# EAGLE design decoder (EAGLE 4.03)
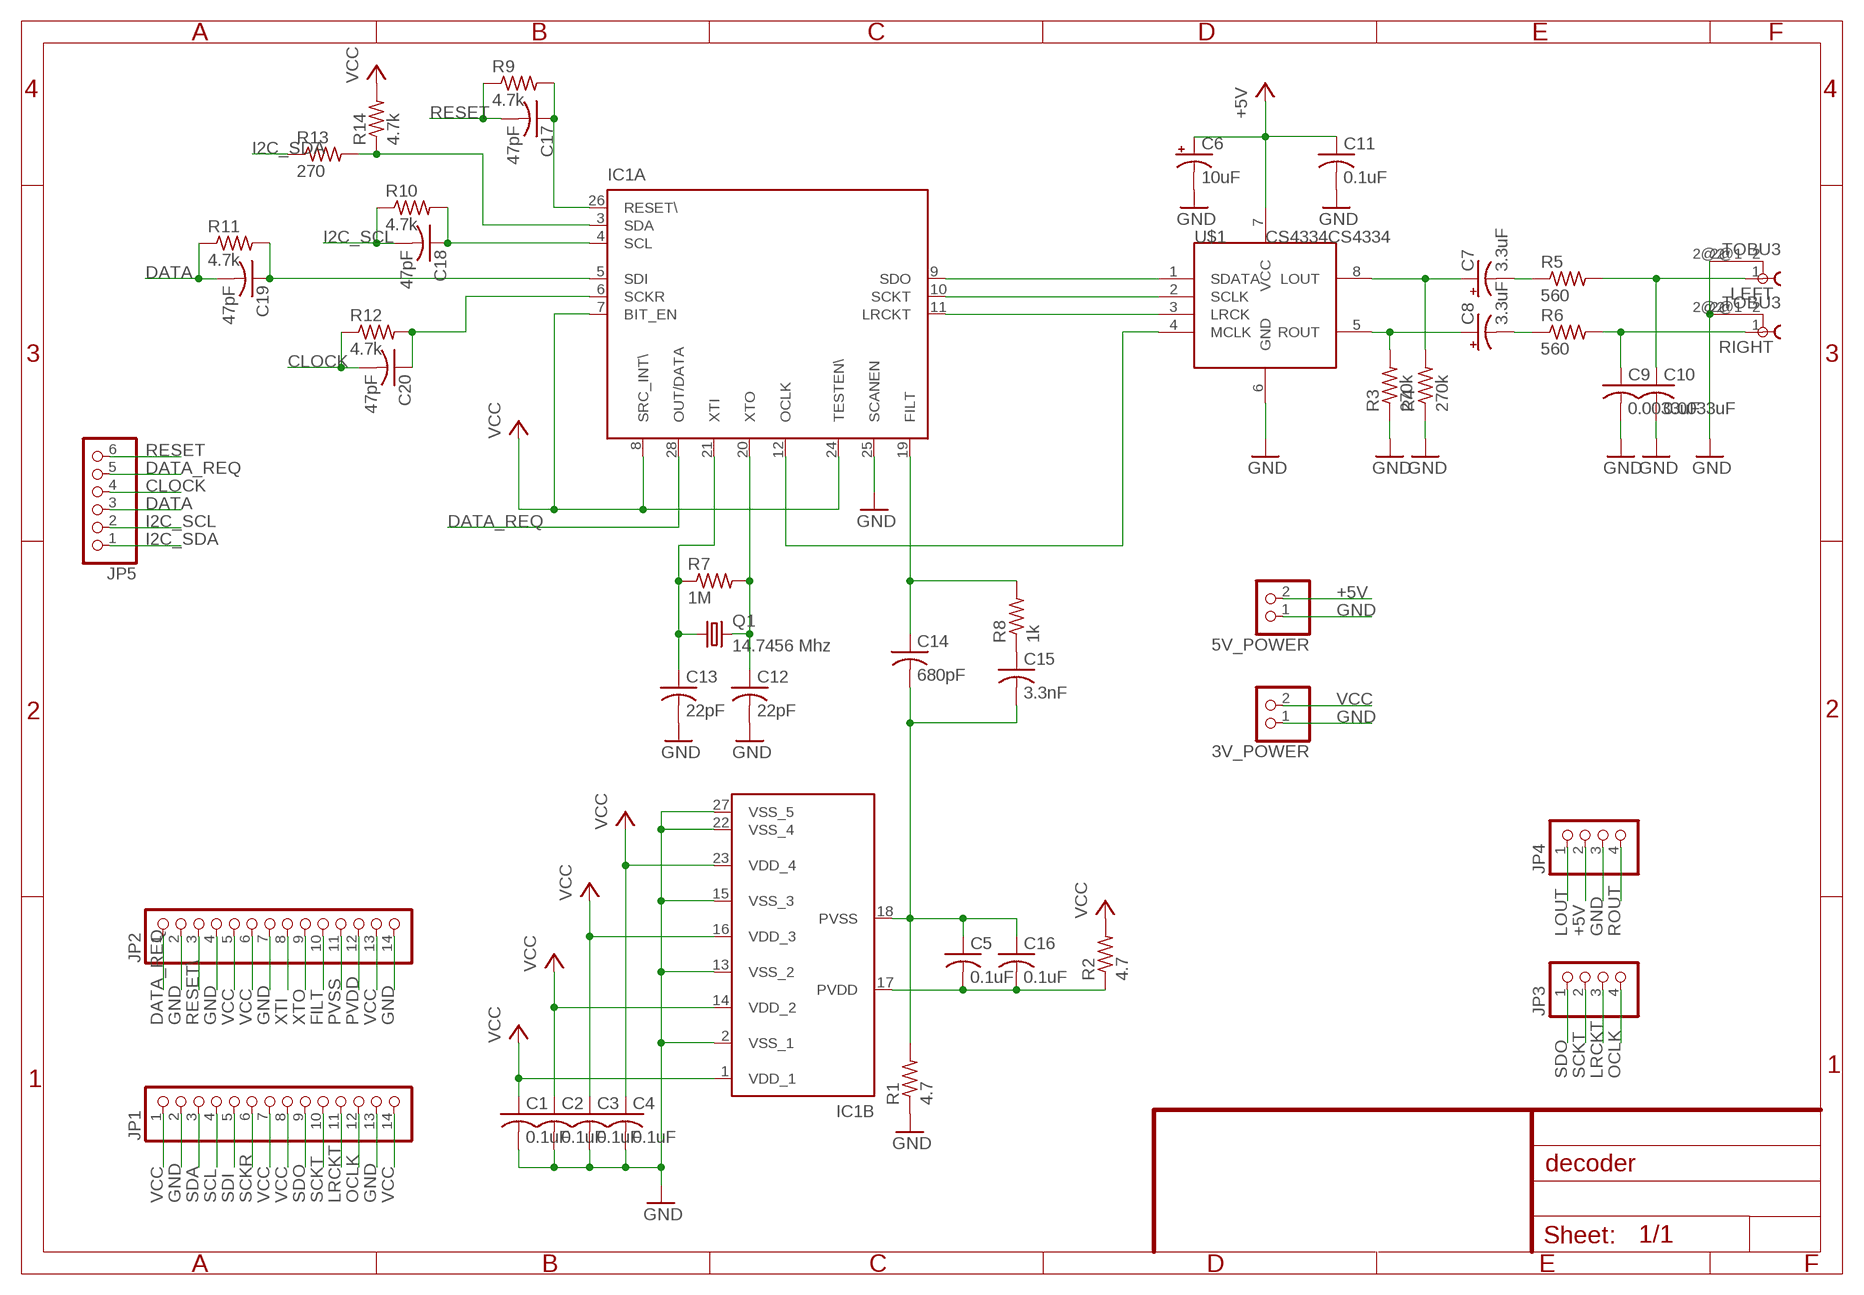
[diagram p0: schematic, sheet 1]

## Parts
3V_POWER  PINHD-1X2  [1X02]
5V_POWER  PINHD-1X2  [1X02]
C1  0.1uF  C-US050-025X075  [C050-025X075]
C2  0.1uF  C-US050-025X075  [C050-025X075]
C3  0.1uF  C-US050-025X075  [C050-025X075]
C4  0.1uF  C-US050-025X075  [C050-025X075]
C5  0.1uF  C-US050-025X075  [C050-025X075]
C6  10uF  CPOL-USTAP5-60  [TAP5-60]
C7  3.3uF  CPOL-USTAP5-60  [TAP5-60]
C8  3.3uF  CPOL-USTAP5-60  [TAP5-60]
C9  0.0033uF  C-US050-025X075  [C050-025X075]
C10  0.0033uF  C-US050-025X075  [C050-025X075]
C11  0.1uF  C-US050-025X075  [C050-025X075]
C12  22pF  C-US050-025X075  [C050-025X075]
C13  22pF  C-US050-025X075  [C050-025X075]
C14  680pF  C-US050-025X075  [C050-025X075]
C15  3.3nF  C-US050-025X075  [C050-025X075]
C16  0.1uF  C-US050-025X075  [C050-025X075]
C17  47pF  C-US050-025X075  [C050-025X075]
C18  47pF  C-US050-025X075  [C050-025X075]
C19  47pF  C-US050-025X075  [C050-025X075]
C20  47pF  C-US050-025X075  [C050-025X075]
IC1  STA013S  [SO28W]
JP1  PINHD-1X14  [1X14]
JP2  PINHD-1X14  [1X14]
JP3  PINHD-1X4  [1X04]
JP4  PINHD-1X4  [1X04]
JP5  PINHD-1X6  [1X06]
LEFT  TOBU3  [TOBU3]
Q1  14.7456 Mhz  HC49U-V  [HC49U-V]
R1  4.7  R-US_0207/10  [0207/10]
R2  4.7  R-US_0207/10  [0207/10]
R3  270k  R-US_0207/10  [0207/10]
R4  270k  R-US_0207/10  [0207/10]
R5  560  R-US_0207/10  [0207/10]
R6  560  R-US_0207/10  [0207/10]
R7  1M  R-US_0207/10  [0207/10]
R8  1k  R-US_0207/10  [0207/10]
R9  4.7k  R-US_0207/10  [0207/10]
R10  4.7k  R-US_0207/10  [0207/10]
R11  4.7k  R-US_0207/10  [0207/10]
R12  4.7k  R-US_0207/10  [0207/10]
R13  270  R-US_0207/10  [0207/10]
R14  4.7k  R-US_0207/10  [0207/10]
RIGHT  TOBU3  [TOBU3]
U$1  CS4334CS4334  [SO08]

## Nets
+5V: 5V_POWER.2 C6.+ C11.1 JP4.2 U$1.7(VCC)
CLOCK: C20.2 JP5.4 R12.1
DATA: C19.2 JP5.3 R11.1
DATA_REQ: IC1.28(A:OUT/DATA) JP2.1 JP5.5
FILT: C14.1 IC1.19(A:FILT) JP2.10 R8.2
GND: 3V_POWER.1 5V_POWER.1 C1.2 C2.2 C3.2 C4.2 C6.- C9.2 C10.2 C11.2 C12.2 C13.2 IC1.2(B:VSS_1) IC1.13(B:VSS_2) IC1.15(B:VSS_3) IC1.22(B:VSS_4) IC1.25(A:SCANEN) IC1.27(B:VSS_5) JP1.2 JP1.13 JP2.2 JP2.4 JP2.7 JP2.14 JP4.3 LEFT.2@2 R1.1 R3.1 R4.1 RIGHT.2@2 U$1.6(GND)
I2C_SCL: C18.2 JP5.2 R10.1
I2C_SDA: JP5.1 R13.1
LOUT: C7.+ JP4.1 R4.2 U$1.8(LOUT)
LRCKT: IC1.11(A:LRCKT) JP1.11 JP3.3 U$1.3(LRCK)
N$1: C15.1 R8.1
N$4: C7.- R5.1
N$5: C8.- R6.1
N$6: C9.1 R6.2 RIGHT.1
N$7: C10.1 LEFT.1 R5.2
OCLK: IC1.12(A:OCLK) JP1.12 JP3.4 U$1.4(MCLK)
PVDD: C5.2 C16.2 IC1.17(B:PVDD) JP2.12 R2.1
PVSS: C5.1 C14.2 C15.2 C16.1 IC1.18(B:PVSS) JP2.11 R1.2
RESET: C17.2 JP5.6 R9.1
RESET\: C17.1 IC1.26(A:RESET\) JP2.3 R9.2
ROUT: C8.+ JP4.4 R3.2 U$1.5(ROUT)
SCKR: C20.1 IC1.6(A:SCKR) JP1.6 R12.2
SCKT: IC1.10(A:SCKT) JP1.10 JP3.2 U$1.2(SCLK)
SCL: C18.1 IC1.4(A:SCL) JP1.4 R10.2
SDA: IC1.3(A:SDA) JP1.3 R13.2 R14.1
SDI: C19.1 IC1.5(A:SDI) JP1.5 R11.2
SDO: IC1.9(A:SDO) JP1.9 JP3.1 U$1.1(SDATA)
VCC: 3V_POWER.2 C1.1 C2.1 C3.1 C4.1 IC1.1(B:VDD_1) IC1.7(A:BIT_EN) IC1.8(A:SRC_INT\) IC1.14(B:VDD_2) IC1.16(B:VDD_3) IC1.23(B:VDD_4) IC1.24(A:TESTEN\) JP1.1 JP1.7 JP1.8 JP1.14 JP2.5 JP2.6 JP2.13 R2.2 R14.2
XTI: C13.1 IC1.21(A:XTI) JP2.8 Q1.1 R7.1
XTO: C12.1 IC1.20(A:XTO) JP2.9 Q1.2 R7.2
Unconnected: LEFT.2 LEFT.2@1 RIGHT.2 RIGHT.2@1

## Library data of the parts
3V_POWER 5V_POWER = pinhead:PINHD-1X2: PIN HEADER
C1-C5 C9-C20 = rcl:C-US: CAPACITOR, American symbol
C6-C8 = rcl:CPOL-US: POLARIZED CAPACITOR, American symbol
IC1 = st-microelectronics:STA013S: MP3 AUDIO DECODER
JP1 JP2 = pinhead:PINHD-1X14: PIN HEADER
JP3 JP4 = pinhead:PINHD-1X4: PIN HEADER
JP5 = pinhead:PINHD-1X6: PIN HEADER
LEFT RIGHT = con-hirschmann:TOBU3: Female Cinch CONNECTOR
Q1 = crystal:HC49U-V: CRYSTAL
R1-R14 = rcl:R-US_: RESISTOR, American symbol
U$1 = scott:CS4334

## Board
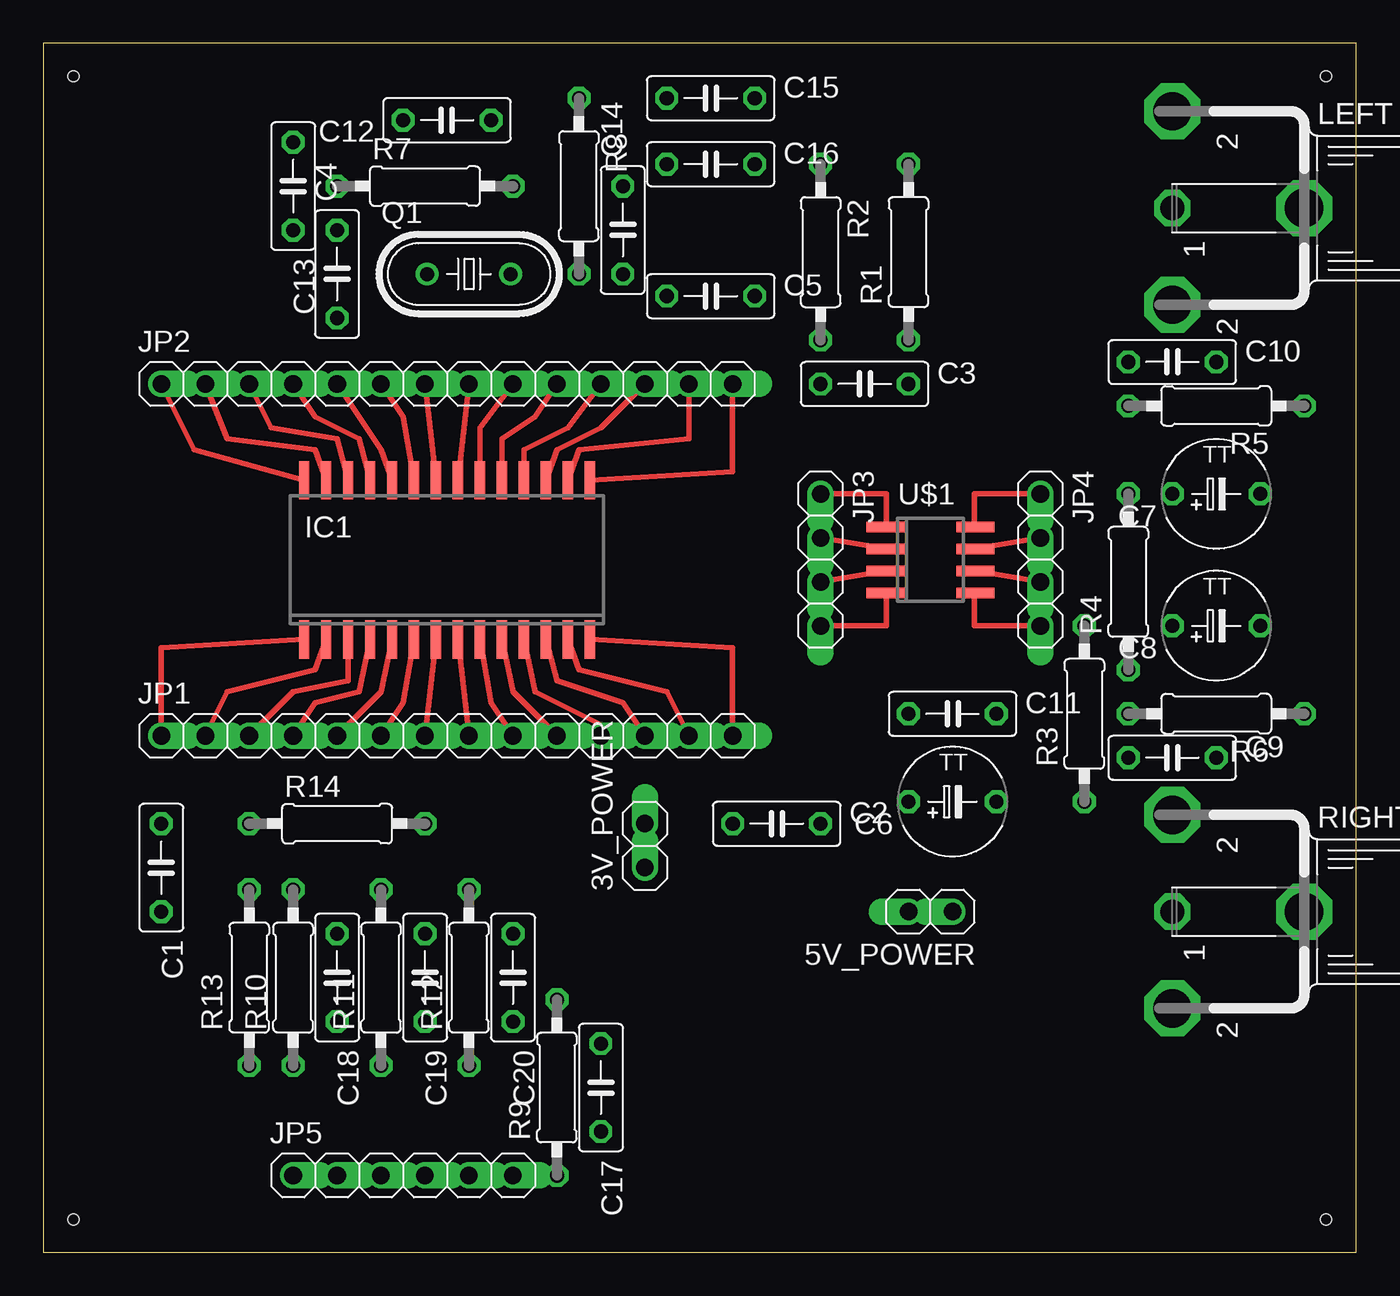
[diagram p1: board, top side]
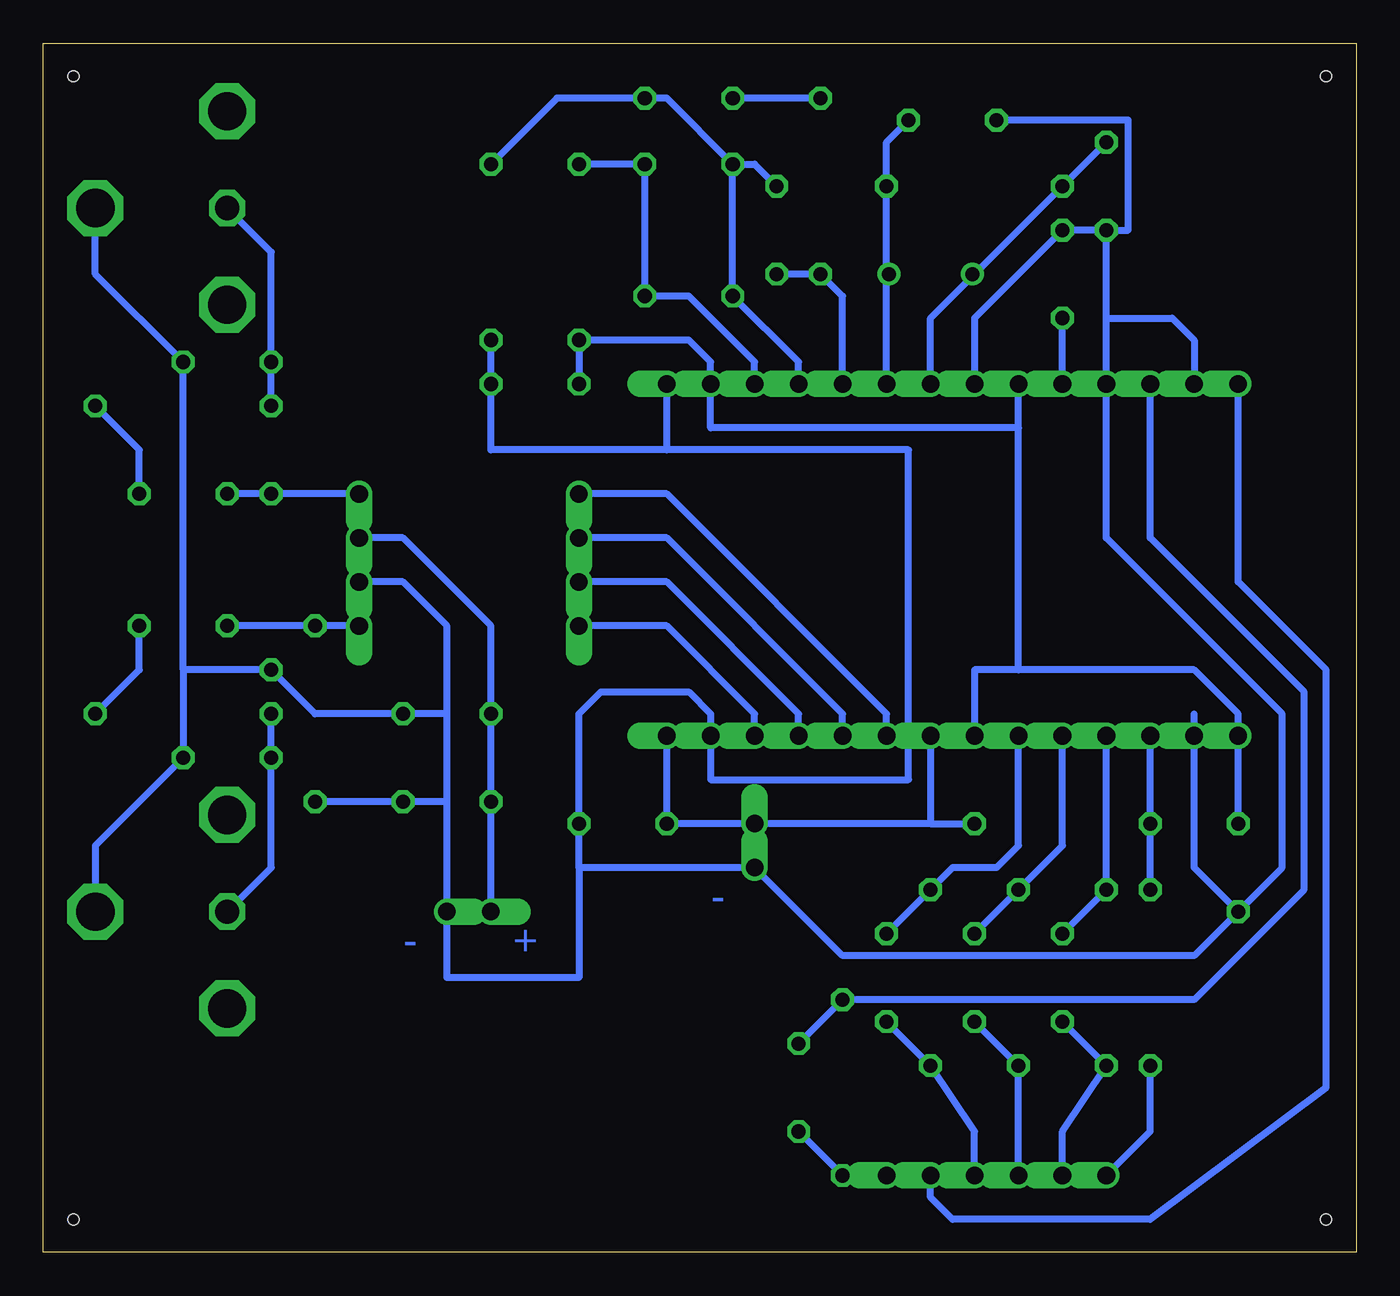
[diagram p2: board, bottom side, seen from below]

Size 75.87 x 69.84 mm. Coordinates in mm from the lower left corner, seen from the top.
Outline: 0,0 75.87,0 75.87,69.84 0,69.84 0,0
Copper layers used: Top, Bottom
Holes 0.61 mm at 1.74,1.9 1.74,67.94 74.13,67.94 74.13,1.9

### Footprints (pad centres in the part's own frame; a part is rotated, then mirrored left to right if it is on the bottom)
1X02 = drill 1.016 offset: 1 -1.27,0; 2 1.27,0
C050-025X075 = drill 0.813 octagon: 1 -2.54,0; 2 2.54,0
TAP5-60 = drill 0.813 octagon: + 2.54,0; - -2.54,0
SO28W = smd 0.6 x 2.2: 1 -8.255,-4.6; 2 -6.985,-4.6; 3 -5.715,-4.6; 4 -4.445,-4.6; 5 -3.175,-4.6; 6 -1.905,-4.6; 7 -0.635,-4.6; 8 0.635,-4.6; 9 1.905,-4.6; 10 3.175,-4.6; 11 4.445,-4.6; 12 5.715,-4.6; 13 6.985,-4.6; 14 8.255,-4.6; 15 8.255,4.6; 16 6.985,4.6; 17 5.715,4.6; 18 4.445,4.6; 19 3.175,4.6; 20 1.905,4.6; 21 0.635,4.6; 22 -0.635,4.6; 23 -1.905,4.6; 24 -3.175,4.6; 25 -4.445,4.6; 26 -5.715,4.6; 27 -6.985,4.6; 28 -8.255,4.6
1X14 = drill 1.016 offset: 1 -16.51,0; 2 -13.97,0; 3 -11.43,0; 4 -8.89,0; 5 -6.35,0; 6 -3.81,0; 7 -1.27,0; 8 1.27,0; 9 3.81,0; 10 6.35,0; 11 8.89,0; 12 11.43,0; 13 13.97,0; 14 16.51,0
1X04 = drill 1.016 offset: 1 -3.81,0; 2 -1.27,0; 3 1.27,0; 4 3.81,0
1X06 = drill 1.016 offset: 1 -6.35,0; 2 -3.81,0; 3 -1.27,0; 4 1.27,0; 5 3.81,0; 6 6.35,0
TOBU3 = drill 1.397 octagon: 1 0,-2.54 | drill 2.21 octagon: 2 5.588,-2.54; 2@1 -5.588,-2.54; 2@2 0,5.08
HC49U-V = drill 0.813 round: 1 -2.413,0; 2 2.413,0
0207/10 = drill 0.813 octagon: 1 -5.08,0; 2 5.08,0
SO08 = smd 0.6 x 2.2: 1 -1.905,-2.6; 2 -0.635,-2.6; 3 0.635,-2.6; 4 1.905,-2.6; 5 1.905,2.6; 6 0.635,2.6; 7 -0.635,2.6; 8 -1.905,2.6

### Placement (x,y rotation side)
3V_POWER  34.76,23.49 90 top
5V_POWER  51.27,19.68 180 top
C1  6.82,22.22 270 top
C2  42.38,24.76 0 top
C3  47.46,50.16 0 top
C4  16.98,56.51 90 top
C5  38.57,55.24 0 top
C6  52.54,26.03 180 top
C7  67.78,43.81 180 top
C8  67.78,36.19 180 top
C9  65.24,28.57 0 top
C10  65.24,51.43 0 top
C11  52.54,31.11 0 top
C12  23.33,65.4 180 top
C13  14.44,61.59 270 top
C14  33.49,59.05 90 top
C15  38.57,66.67 0 top
C16  38.57,62.86 0 top
C17  32.22,9.52 270 top
C18  16.98,15.87 270 top
C19  22.06,15.87 270 top
C20  27.14,15.87 270 top
IC1  23.33,40 0 top
JP1  23.33,29.84 0 top
JP2  23.33,50.16 0 top
JP3  44.92,40 270 top
JP4  57.62,40 270 top
JP5  20.79,4.44 0 top
LEFT  67.78,60.32 270 top
Q1  24.6,56.51 0 top
R1  50,57.78 90 top
R2  44.92,57.78 270 top
R3  60.16,31.11 90 top
R4  62.7,38.73 90 top
R5  67.78,48.89 180 top
R6  67.78,31.11 180 top
R7  22.06,61.59 0 top
R8  30.95,61.59 270 top
R9  29.68,9.52 90 top
R10  14.44,15.87 90 top
R11  19.52,15.87 90 top
R12  24.6,15.87 90 top
R13  11.9,15.87 90 top
R14  16.98,24.76 0 top
RIGHT  67.78,19.68 270 top
U$1  51.27,40 270 top

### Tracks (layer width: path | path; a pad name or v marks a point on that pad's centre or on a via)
+5V
  Top 0.305: JP4.2 U$1.7
  Bottom 0.406: 5V_POWER.2 C6.+ C11.1 50,36.19 55.08,41.27 JP4.2
CLOCK
  Bottom 0.406: JP5.4 22.06,6.98 R12.1 C20.2
DATA
  Bottom 0.406: JP5.3 R11.1 C19.2
DATA_REQ
  Top 0.305: IC1.28 8.73,46.35 JP2.1
  Bottom 0.406: JP5.5 24.6,3.17 23.33,1.9 11.9,1.9 1.74,9.52 1.74,33.65 6.82,38.73 JP2.1
FILT
  Top 0.305: IC1.19 26.5,46.98 28.41,48.26 JP2.10
  Bottom 0.406: JP2.10 29.68,55.24 R8.2 C14.1
GND
  Top 0.305: JP4.3 U$1.6 | JP2.7 IC1.22 | IC1.25 18.25,46.98 15.71,48.26 JP2.4 | IC1.27 15.71,46.35 10.63,46.98 JP2.2 | IC1.15 39.84,45.08 JP2.14 | IC1.13 30.95,33.65 36.03,32.38 JP1.13 | IC1.2 15.71,33.65 10.63,32.38 JP1.2
  Bottom 0.406: 9.36,31.11 JP1.2 9.36,22.22 C1.2 | 52.54,26.03 5V_POWER.1 52.54,15.87 44.92,15.87 44.92,22.22 | 52.54,26.03 52.54,31.11 | 52.54,26.03 C6.- R3.1 | 52.54,31.11 C11.2 60.16,31.11 R4.1 67.78,33.65 | 52.54,31.11 52.54,36.19 55.08,38.73 JP4.3 | 39.84,46.35 25.87,46.35 25.87,27.3 37.3,27.3 JP1.13 37.3,31.11 38.57,32.38 43.65,32.38 44.92,31.11 C2.2 44.92,22.22 | 39.84,46.35 JP2.14 | 14.44,53.97 C13.2 | R1.1 C3.2 50,46.35 39.84,46.35 | 44.92,22.22 3V_POWER.1 29.68,17.14 9.36,17.14 C1.2 | 14.44,53.97 JP2.4 14.44,41.27 4.28,31.11 4.28,22.22 C1.2 | JP2.2 9.36,52.7 10.63,53.97 14.44,53.97 | JP2.7 22.06,53.97 C4.2 C13.2 | C12.2 13.17,65.4 13.17,59.05 C13.2 | RIGHT.2@2 72.86,23.49 C9.2 67.78,33.65 | 67.78,33.65 C10.2 72.86,56.51 LEFT.2@2
I2C_SCL
  Bottom 0.406: JP5.2 16.98,6.98 R10.1 C18.2
I2C_SDA
  Bottom 0.406: JP5.1 11.9,6.98 R13.1
LOUT
  Top 0.305: U$1.8 53.81,41.91 53.81,43.81 JP4.1
  Bottom 0.406: JP4.1 R4.2 C7.+
LRCKT
  Top 0.305: U$1.3 48.73,39.37 JP3.3 | IC1.11 28.41,32.38 32.22,30.47 JP1.11
  Bottom 0.406: JP3.3 39.84,38.73 32.22,31.11 JP1.11
N$1
  Bottom 0.406: R8.1 C15.1
N$4
  Bottom 0.406: C7.- 70.32,46.35 R5.1
N$5
  Bottom 0.406: C8.- 70.32,33.65 R6.1
N$6
  Bottom 0.406: R6.2 C9.1 62.7,22.22 RIGHT.1
N$7
  Bottom 0.406: R5.2 C10.1 62.7,57.78 LEFT.1
OCLK
  Top 0.305: U$1.4 48.73,38.1 48.73,36.19 JP3.4 | IC1.12 29.68,33.02 33.49,31.74 JP1.12
  Bottom 0.406: JP1.12 34.76,31.11 39.84,36.19 JP3.4
PVDD
  Top 0.305: IC1.17 29.68,46.35 32.22,47.62 JP2.12
  Bottom 0.406: R2.1 C16.2 C5.2 38.57,55.24 34.76,51.43 JP2.12
PVSS
  Top 0.305: IC1.18 27.77,46.35 30.31,47.62 JP2.11
  Bottom 0.406: C16.1 C5.1 32.22,51.43 JP2.11 | C14.2 34.76,62.86 C16.1 | C16.1 39.84,66.67 C15.2 46.19,66.67 R1.2
RESET
  Bottom 0.406: JP5.6 R9.1 C17.2
RESET\
  Top 0.305: IC1.26 16.98,46.98 13.17,47.62 JP2.3
  Bottom 0.406: JP2.3 11.9,41.27 3.01,32.38 3.01,20.95 9.36,14.6 R9.2 C17.1
ROUT
  Top 0.305: U$1.5 53.81,38.1 53.81,36.19 JP4.4
  Bottom 0.406: JP4.4 R3.2 C8.+
SCKR
  Top 0.305: IC1.6 20.79,31.74 JP1.6
  Bottom 0.406: C20.1 R12.2 23.33,22.22 20.79,22.22 19.52,23.49 JP1.6
SCKT
  Top 0.305: U$1.2 48.73,40.64 JP3.2 | IC1.10 27.14,32.38 JP1.10
  Bottom 0.406: JP3.2 39.84,41.27 29.68,31.11 JP1.10
SCL
  Top 0.305: IC1.4 18.25,32.38 15.71,31.74 JP1.4
  Bottom 0.406: C18.1 R10.2 JP1.4
SDA
  Top 0.305: IC1.3 17.61,33.02 14.44,32.38 JP1.3
  Bottom 0.406: JP1.3 R14.1 R13.2
SDI
  Top 0.305: IC1.5 19.52,32.38 JP1.5
  Bottom 0.406: C19.1 R11.2 16.98,23.49 JP1.5
SDO
  Top 0.305: U$1.1 48.73,41.91 48.73,43.81 JP3.1 | IC1.9 25.87,31.74 JP1.9
  Bottom 0.406: JP3.1 39.84,43.81 27.14,31.11 JP1.9
VCC
  Top 0.305: IC1.23 20.79,48.26 JP2.6 | IC1.24 19.52,46.35 JP2.5 | IC1.16 30.95,46.35 37.3,46.98 JP2.13 | IC1.14 39.84,34.92 JP1.14 | JP1.8 IC1.8 | JP1.7 IC1.7 | IC1.1 6.82,34.92 JP1.1
  Bottom 0.406: 19.52,33.65 9.36,33.65 6.82,31.11 JP1.1 C1.1 | 19.52,33.65 22.06,33.65 JP1.7 JP1.8 24.6,24.76 | JP1.14 C2.1 3V_POWER.2 24.6,24.76 | C3.1 R2.2 38.57,52.7 37.3,51.43 JP2.13 37.3,47.62 19.52,47.62 | 19.52,33.65 19.52,47.62 | 19.52,47.62 JP2.6 JP2.5 C4.1 | 24.6,24.76 R14.2
XTI
  Top 0.305: IC1.21 JP2.8
  Bottom 0.406: 22.06,56.51 Q1.1 | JP2.8 24.6,53.97 22.06,56.51 | 22.06,56.51 R7.1 C13.1
XTO
  Top 0.305: IC1.20 25.23,47.62 JP2.9
  Bottom 0.406: JP2.9 27.14,56.51 | 27.14,56.51 Q1.2 | 27.14,56.51 R7.2 27.14,64.13 C12.1

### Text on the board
Bottom: - | + | -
